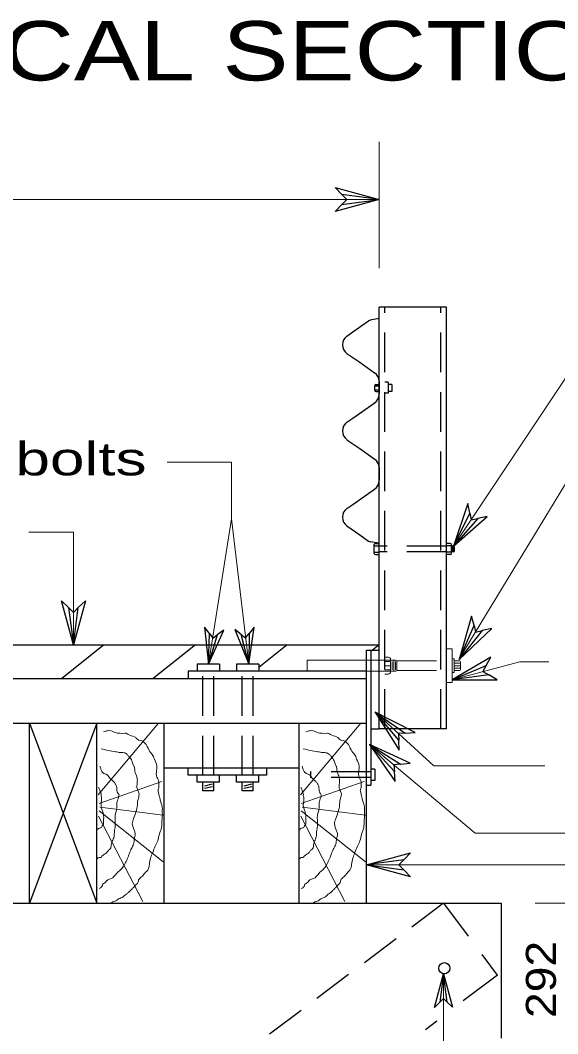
# Model space of a CAD drawing. Extents: x 13426 to 15509, y -9298 to -5111.
# Drawn here: x 15398.12 to 15419.29, y -5515.72 to -5475.82 of the extents above; entities that cross this region are included whole.
import ezdxf
from ezdxf.enums import TextEntityAlignment as Align

# ---------------------------------------------------------------- set-up
doc = ezdxf.new("R2010")
doc.units = 0
doc.header["$LTSCALE"] = 0.52
doc.linetypes.add('MEDIUM_DASHED', pattern=[4.5, 3, -1.5])
for name, color, linetype, lineweight in [('1', 7, 'Continuous', 13), ('15', 7, 'Continuous', 13), ('16', 7, 'Continuous', 25), ('2', 7, 'Continuous', 25), ('20', 7, 'Continuous', 13), ('3', 7, 'Continuous', 25), ('4', 7, 'Continuous', 13), ('5', 7, 'Continuous', 25)]:
    doc.layers.add(name, color=color, linetype=linetype, lineweight=lineweight)
doc.layers.add('19', color=7, linetype='Continuous')

msp = doc.modelspace()

# ---------------------------------------------------------------- linework, layer by layer
at = {"layer": '1'}
for p, q in [((15412.258, -5480.613), (15412.258, -5485.587)), ((15412.258, -5482.878), (15347.53, -5482.878))]:
    msp.add_line(p, q, dxfattribs=at)
at = {"layer": '1', "lineweight": 25}
for p, q in [((15411.219, -5488.094), (15411.843, -5487.655)), ((15412.258, -5487.565), (15411.911, -5487.626)), ((15410.99, -5488.252), (15411.218, -5488.092)), ((15410.99, -5488.939), (15411.493, -5489.286)), ((15411.493, -5489.287), (15412.08, -5489.7)), ((15412.258, -5490.546), (15412.258, -5490.043)), ((15412.258, -5490.043), (15412.258, -5490.546)), ((15411.216, -5491.487), (15412.104, -5490.873)), ((15410.99, -5491.65), (15411.218, -5491.491)), ((15410.99, -5492.333), (15411.492, -5492.684)), ((15411.493, -5492.682), (15412.104, -5493.11)), ((15412.258, -5493.434), (15412.258, -5493.933)), ((15412.258, -5493.933), (15412.258, -5493.434)), ((15410.99, -5495.726), (15411.492, -5496.078)), ((15411.493, -5496.077), (15411.843, -5496.326)), ((15412.257, -5496.413), (15411.91, -5496.354))]:
    msp.add_line(p, q, dxfattribs=at)
for points in [[(15410.99, -5495.043), (15411.218, -5494.884), (15412.08, -5494.281)], [(15342.717, -5510.579), (15417.071, -5510.579), (15417.071, -5515.89)]]:
    msp.add_lwpolyline(points, dxfattribs=at)
for centre, radius, start, end in [((15411.9413, -5487.7915), 0.1669, 100.00085, 124.99926), ((15411.2299, -5488.5954), 0.4173, 124.98392, 235.01553), ((15411.8419, -5490.0422), 0.4173, 359.99953, 55.01553), ((15411.8419, -5490.543), 0.4173, 304.98447, 0.00048), ((15411.2299, -5491.9897), 0.4173, 124.98392, 235.01552), ((15411.2299, -5491.9898), 0.4173, 124.98445, 235.01605), ((15411.8419, -5493.4365), 0.4173, 359.99946, 55.01547), ((15411.8419, -5493.9373), 0.4173, 304.98441, 0.00041), ((15411.2299, -5495.3841), 0.4173, 124.98445, 235.01605), ((15411.939, -5496.1891), 0.1669, 235.00071, 259.99912)]:
    msp.add_arc(centre, radius, start, end, dxfattribs=at)
at = {"layer": '15'}
for p, q in [((15421.463, -5487.1), (15415.189, -5496.522)), ((15406.44, -5493.222), (15403.914, -5493.222)), ((15406.44, -5495.443), (15406.44, -5493.222)), ((15415.416, -5500.962), (15419.597, -5494.065)), ((15405.541, -5501.172), (15406.44, -5495.443)), ((15407.124, -5501.174), (15406.441, -5495.443)), ((15412.103, -5503.054), (15414.407, -5505.17)), ((15411.881, -5504.332), (15416.047, -5507.828)), ((15414.407, -5505.17), (15418.785, -5505.17)), ((15416.047, -5507.828), (15426.412, -5507.828)), ((15411.76, -5509.07), (15425.591, -5509.07)), ((15418.411, -5510.579), (15424.564, -5510.579)), ((15414.792, -5513.359), (15414.796, -5516.375))]:
    msp.add_line(p, q, dxfattribs=at)
at = {"layer": '15', "lineweight": 25}
for p, q in [((15412.134, -5490.156), (15412.258, -5490.156)), ((15412.089, -5490.218), (15412.258, -5490.218)), ((15412.089, -5490.368), (15412.258, -5490.368)), ((15412.134, -5490.433), (15412.258, -5490.433))]:
    msp.add_line(p, q, dxfattribs=at)
at = {"layer": '15', "linetype": 'MEDIUM_DASHED', "lineweight": 25}
for p, q in [((15412.753, -5490.156), (15412.612, -5490.156)), ((15412.753, -5490.433), (15412.612, -5490.433))]:
    msp.add_line(p, q, dxfattribs=at)
at = {"layer": '15'}
for points in [[(15398.461, -5495.973), (15400.214, -5495.973), (15400.214, -5500.409)], [(15415.135, -5501.785), (15417.796, -5501.074), (15418.945, -5501.074)]]:
    msp.add_lwpolyline(points, dxfattribs=at)
at = {"layer": '16'}
for points in [[(15410.794, -5482.687), (15410.523, -5482.405), (15412.258, -5482.878), (15410.523, -5483.351), (15410.794, -5483.069), (15412.258, -5482.878), (15410.794, -5482.687), (15410.985, -5482.878), (15410.794, -5483.069)], [(15415.829, -5495.221), (15415.746, -5494.847), (15415.189, -5496.522), (15416.52, -5495.362), (15416.143, -5495.429), (15415.189, -5496.522), (15415.829, -5495.221), (15415.882, -5495.482), (15416.143, -5495.429)], [(15400.405, -5498.945), (15400.687, -5498.674), (15400.214, -5500.409), (15399.74, -5498.674), (15400.022, -5498.945), (15400.214, -5500.409), (15400.405, -5498.945), (15400.214, -5499.136), (15400.022, -5498.945)], [(15415.996, -5499.653), (15415.897, -5499.283), (15415.411, -5500.981), (15416.692, -5499.764), (15416.318, -5499.848), (15415.411, -5500.981), (15415.996, -5499.653), (15416.059, -5499.912), (15416.318, -5499.848)], [(15405.571, -5499.963), (15405.378, -5499.709), (15405.541, -5501.172), (15406.143, -5499.829), (15405.881, -5500.012), (15405.541, -5501.172), (15405.571, -5499.963), (15405.702, -5500.143), (15405.881, -5500.012)], [(15406.823, -5500), (15406.568, -5499.807), (15407.12, -5501.172), (15407.337, -5499.716), (15407.134, -5499.963), (15407.12, -5501.172), (15406.823, -5500), (15406.997, -5500.137), (15407.134, -5499.963)], [(15416.474, -5501.225), (15416.657, -5500.888), (15415.135, -5501.785), (15416.902, -5501.785), (15416.573, -5501.588), (15415.135, -5501.785), (15416.474, -5501.225), (15416.341, -5501.456), (15416.573, -5501.588)], [(15413.29, -5503.889), (15413.673, -5503.865), (15412.103, -5503.054), (15413.044, -5504.549), (15413.036, -5504.166), (15412.103, -5503.054), (15413.29, -5503.889), (15413.024, -5503.9), (15413.036, -5504.166)], [(15413.103, -5505.112), (15413.485, -5505.071), (15411.881, -5504.332), (15412.887, -5505.783), (15412.861, -5505.401), (15411.881, -5504.332), (15413.103, -5505.112), (15412.839, -5505.135), (15412.861, -5505.401)], [(15413.225, -5509.261), (15413.495, -5509.543), (15411.76, -5509.07), (15413.495, -5508.596), (15413.225, -5508.878), (15411.76, -5509.07), (15413.225, -5509.261), (15413.033, -5509.07), (15413.225, -5508.878)], [(15414.648, -5514.472), (15414.434, -5514.678), (15414.792, -5513.359), (15415.153, -5514.677), (15414.939, -5514.472), (15414.792, -5513.359), (15414.648, -5514.472), (15414.793, -5514.326), (15414.939, -5514.472)]]:
    msp.add_lwpolyline(points, dxfattribs=at)
at = {"layer": '2'}
for p, q in [((15405.974, -5501.174), (15405.088, -5501.174)), ((15405.088, -5501.174), (15405.088, -5501.451)), ((15405.974, -5501.174), (15405.974, -5501.451)), ((15407.523, -5501.174), (15406.638, -5501.174)), ((15406.638, -5501.174), (15406.638, -5501.451)), ((15407.523, -5501.174), (15407.523, -5501.451)), ((15412.093, -5505.301), (15411.926, -5505.301)), ((15412.093, -5505.301), (15412.093, -5505.744)), ((15405.088, -5505.821), (15405.088, -5505.545)), ((15405.974, -5505.821), (15405.974, -5505.545)), ((15406.638, -5505.821), (15406.638, -5505.545)), ((15407.523, -5505.821), (15407.523, -5505.545)), ((15405.974, -5505.821), (15405.088, -5505.821)), ((15405.31, -5506.153), (15405.31, -5505.821)), ((15405.687, -5505.89), (15405.38, -5505.966)), ((15405.689, -5505.992), (15405.381, -5506.069)), ((15405.752, -5506.153), (15405.752, -5505.821)), ((15407.523, -5505.821), (15406.638, -5505.821)), ((15406.859, -5506.153), (15406.859, -5505.821)), ((15407.236, -5505.89), (15406.929, -5505.966)), ((15407.238, -5505.992), (15406.93, -5506.069)), ((15407.301, -5506.153), (15407.301, -5505.821)), ((15412.093, -5505.744), (15411.926, -5505.744)), ((15405.752, -5506.153), (15405.31, -5506.153)), ((15407.301, -5506.153), (15406.859, -5506.153)), ((15414.798, -5510.579), (15415.771, -5511.873)), ((15416.926, -5513.41), (15416.312, -5512.592)), ((15416.926, -5513.41), (15415.57, -5514.428)), ((15414.085, -5515.544), (15414.536, -5515.206))]:
    msp.add_line(p, q, dxfattribs=at)
at = {"layer": '2', "linetype": 'MEDIUM_DASHED'}
for p, q in [((15405.31, -5505.545), (15405.31, -5501.451)), ((15405.752, -5505.545), (15405.752, -5501.451)), ((15406.859, -5505.545), (15406.859, -5501.451)), ((15407.301, -5505.545), (15407.301, -5501.451)), ((15411.926, -5505.633), (15409.548, -5505.633)), ((15414.798, -5510.579), (15406.892, -5516.522))]:
    msp.add_line(p, q, dxfattribs=at)
msp.add_lwpolyline([(15411.926, -5505.412), (15409.548, -5505.412), (15409.548, -5505.633)], dxfattribs=at)
at = {"layer": '2'}
msp.add_circle((15414.8272, -5513.1405), 0.2213, dxfattribs=at)
at = {"layer": '3', "linetype": 'MEDIUM_DASHED'}
for p, q in [((15412.612, -5490.07), (15412.479, -5490.07)), ((15412.612, -5490.07), (15412.612, -5490.507)), ((15412.753, -5490.156), (15412.753, -5490.433)), ((15412.612, -5490.507), (15412.479, -5490.507)), ((15414.913, -5496.522), (15412.258, -5496.522)), ((15414.913, -5496.744), (15412.258, -5496.744))]:
    msp.add_line(p, q, dxfattribs=at)
at = {"layer": '3'}
for p, q in [((15412.089, -5490.388), (15412.089, -5490.2)), ((15412.067, -5496.807), (15412.067, -5496.458)), ((15412.067, -5496.51), (15412.258, -5496.51)), ((15412.112, -5496.414), (15412.257, -5496.414)), ((15415.104, -5496.51), (15414.913, -5496.51)), ((15415.059, -5496.414), (15414.914, -5496.414)), ((15415.104, -5496.807), (15415.104, -5496.458)), ((15415.189, -5496.522), (15415.105, -5496.522)), ((15415.132, -5496.554), (15415.132, -5496.714)), ((15415.179, -5496.554), (15415.179, -5496.714)), ((15412.067, -5496.759), (15412.258, -5496.759)), ((15412.112, -5496.851), (15412.257, -5496.851)), ((15415.104, -5496.759), (15414.913, -5496.759)), ((15415.059, -5496.851), (15414.914, -5496.851)), ((15415.189, -5496.744), (15415.105, -5496.744)), ((15415.233, -5496.699), (15415.233, -5496.566))]:
    msp.add_line(p, q, dxfattribs=at)
for centre, start, end in [((15412.1337, -5490.2002), 90, 180), ((15412.1337, -5490.3882), 180, 270.00003), ((15412.1116, -5496.4581), 90, 180), ((15415.0592, -5496.4581), 0, 90), ((15415.1886, -5496.5666), 0, 90), ((15412.1116, -5496.8073), 180, 269.99999), ((15415.0592, -5496.8073), 270, 0), ((15415.1886, -5496.6994), 270, 0)]:
    msp.add_arc(centre, 0.0443, start, end, dxfattribs=at)
at = {"layer": '4', "lineweight": 25}
for p, q in [((15347.53, -5500.409), (15412.258, -5500.409)), ((15399.743, -5501.728), (15401.4, -5500.409)), ((15405.019, -5500.409), (15403.363, -5501.728)), ((15408.639, -5500.409), (15407.523, -5501.298)), ((15412.258, -5500.409), (15411.992, -5500.621)), ((15348.028, -5501.728), (15411.76, -5501.728)), ((15411.76, -5501.451), (15404.74, -5501.451)), ((15404.74, -5501.451), (15404.74, -5501.728)), ((15411.76, -5510.579), (15411.76, -5501.728)), ((15348.028, -5503.498), (15411.76, -5503.498)), ((15398.483, -5510.579), (15398.483, -5503.498)), ((15398.483, -5503.498), (15401.138, -5510.579)), ((15401.138, -5503.498), (15398.483, -5510.579)), ((15401.138, -5510.579), (15401.138, -5503.498)), ((15403.794, -5510.579), (15403.794, -5503.498)), ((15409.105, -5510.579), (15409.105, -5503.498)), ((15409.105, -5505.268), (15403.794, -5505.268)), ((15404.74, -5505.545), (15404.74, -5505.268)), ((15407.82, -5505.268), (15407.82, -5505.545)), ((15407.82, -5505.545), (15404.74, -5505.545))]:
    msp.add_line(p, q, dxfattribs=at)
at = {"layer": '4'}
for p, q in [((15412.622, -5500.898), (15412.48, -5500.898)), ((15415.135, -5500.567), (15414.914, -5500.567)), ((15415.135, -5500.567), (15415.135, -5501.895)), ((15409.42, -5501.008), (15409.42, -5501.451)), ((15409.42, -5501.008), (15411.76, -5501.008)), ((15412.479, -5501.229), (15412.711, -5501.229)), ((15412.48, -5501.064), (15412.711, -5501.064)), ((15412.711, -5501.472), (15412.711, -5500.987)), ((15412.917, -5501.008), (15412.711, -5501.008)), ((15412.772, -5501.064), (15412.772, -5501.395)), ((15412.836, -5501.008), (15412.836, -5501.451)), ((15412.9, -5501.064), (15412.9, -5501.395)), ((15412.961, -5501.407), (15412.961, -5501.052)), ((15415.218, -5500.954), (15415.135, -5500.954)), ((15415.218, -5500.954), (15415.218, -5501.495)), ((15415.422, -5501.037), (15415.218, -5501.037)), ((15415.218, -5501.134), (15415.466, -5501.134)), ((15415.218, -5501.231), (15415.466, -5501.231)), ((15415.218, -5501.328), (15415.466, -5501.328)), ((15415.466, -5501.38), (15415.466, -5501.081)), ((15412.479, -5501.395), (15412.711, -5501.395)), ((15412.622, -5501.56), (15412.48, -5501.56)), ((15412.917, -5501.451), (15412.711, -5501.451)), ((15415.218, -5501.495), (15415.135, -5501.495)), ((15415.422, -5501.425), (15415.218, -5501.425)), ((15415.135, -5501.895), (15414.914, -5501.895)), ((15403.569, -5503.497), (15401.191, -5506.317)), ((15411.536, -5503.497), (15409.157, -5506.317)), ((15403.701, -5505.79), (15401.223, -5506.657)), ((15411.667, -5505.79), (15409.19, -5506.657)), ((15403.749, -5507.116), (15401.256, -5506.793)), ((15411.716, -5507.116), (15409.223, -5506.793)), ((15402.946, -5510.514), (15401.207, -5507.15)), ((15403.749, -5508.951), (15401.223, -5506.946)), ((15410.912, -5510.514), (15409.173, -5507.15)), ((15411.716, -5508.951), (15409.19, -5506.946))]:
    msp.add_line(p, q, dxfattribs=at)
at = {"layer": '4', "linetype": 'MEDIUM_DASHED'}
for p, q in [((15412.711, -5501.008), (15411.76, -5501.008)), ((15412.958, -5501.037), (15415.218, -5501.037)), ((15411.76, -5501.451), (15412.711, -5501.451)), ((15412.958, -5501.425), (15415.218, -5501.425))]:
    msp.add_line(p, q, dxfattribs=at)
at = {"layer": '4'}
for centre, radius, start, end in [((15412.6225, -5500.987), 0.0885, 0.00001, 90), ((15412.9166, -5501.0524), 0.0443, 0.00001, 90), ((15415.4215, -5501.0814), 0.0443, 0.00001, 90), ((15412.6225, -5501.4719), 0.0885, 270, 0), ((15412.9166, -5501.4065), 0.0443, 270, 0), ((15415.4215, -5501.3801), 0.0443, 270, 0)]:
    msp.add_arc(centre, radius, start, end, dxfattribs=at)
for points in [[(15401.404, -5503.837), (15401.634, -5503.786), (15401.847, -5503.854), (15402.257, -5503.888), (15402.29, -5503.888), (15402.372, -5503.939), (15402.618, -5504.024), (15402.716, -5504.108), (15402.782, -5504.159), (15402.798, -5504.159), (15403.061, -5504.312), (15403.126, -5504.414), (15403.258, -5504.652), (15403.323, -5504.72), (15403.405, -5504.907), (15403.504, -5505.179), (15403.504, -5505.281), (15403.487, -5505.57), (15403.569, -5505.756), (15403.586, -5505.926), (15403.569, -5506.062), (15403.552, -5506.113), (15403.552, -5506.164), (15403.569, -5506.232), (15403.586, -5506.317), (15403.618, -5506.436), (15403.635, -5506.521), (15403.684, -5506.674), (15403.717, -5506.81), (15403.717, -5506.929), (15403.717, -5507.116), (15403.701, -5507.32), (15403.684, -5507.608), (15403.602, -5507.863), (15403.536, -5508.118), (15403.438, -5508.339), (15403.34, -5508.577), (15403.258, -5508.798), (15403.208, -5509.052), (15403.143, -5509.273), (15403.028, -5509.392), (15402.897, -5509.545), (15402.782, -5509.664), (15402.765, -5509.732), (15402.733, -5509.8), (15402.667, -5509.868), (15402.568, -5509.97), (15402.486, -5510.055), (15402.388, -5510.157), (15402.29, -5510.225), (15402.175, -5510.327), (15401.994, -5510.412), (15401.929, -5510.463), (15401.847, -5510.497), (15401.765, -5510.53), (15401.617, -5510.582), (15401.616, -5510.582)], [(15409.37, -5503.837), (15409.6, -5503.786), (15409.813, -5503.854), (15410.223, -5503.888), (15410.256, -5503.888), (15410.338, -5503.939), (15410.584, -5504.024), (15410.683, -5504.108), (15410.748, -5504.159), (15410.765, -5504.159), (15411.027, -5504.312), (15411.093, -5504.414), (15411.224, -5504.652), (15411.29, -5504.72), (15411.372, -5504.907), (15411.47, -5505.179), (15411.47, -5505.281), (15411.454, -5505.57), (15411.536, -5505.756), (15411.552, -5505.926), (15411.536, -5506.062), (15411.519, -5506.113), (15411.519, -5506.164), (15411.536, -5506.232), (15411.552, -5506.317), (15411.585, -5506.436), (15411.601, -5506.521), (15411.651, -5506.674), (15411.683, -5506.81), (15411.683, -5506.929), (15411.683, -5507.116), (15411.667, -5507.32), (15411.651, -5507.608), (15411.569, -5507.863), (15411.503, -5508.118), (15411.404, -5508.339), (15411.306, -5508.577), (15411.224, -5508.798), (15411.175, -5509.052), (15411.109, -5509.273), (15410.994, -5509.392), (15410.863, -5509.545), (15410.748, -5509.664), (15410.732, -5509.732), (15410.699, -5509.8), (15410.633, -5509.868), (15410.535, -5509.97), (15410.453, -5510.055), (15410.354, -5510.157), (15410.256, -5510.225), (15410.141, -5510.327), (15409.961, -5510.412), (15409.895, -5510.463), (15409.813, -5510.497), (15409.731, -5510.53), (15409.584, -5510.582), (15409.582, -5510.582)], [(15401.306, -5504.499), (15401.584, -5504.567), (15401.879, -5504.618), (15401.978, -5504.635), (15402.109, -5504.652), (15402.158, -5504.652), (15402.306, -5504.703), (15402.322, -5504.72), (15402.404, -5504.805), (15402.519, -5504.975), (15402.568, -5505.128), (15402.618, -5505.23), (15402.634, -5505.383), (15402.7, -5505.57), (15402.733, -5505.739), (15402.716, -5505.96), (15402.733, -5506.096), (15402.798, -5506.232), (15402.798, -5506.351), (15402.749, -5506.538), (15402.733, -5506.708), (15402.585, -5507.251), (15402.536, -5507.455), (15402.618, -5507.727), (15402.65, -5507.863), (15402.618, -5508.033), (15402.585, -5508.254), (15402.503, -5508.424), (15402.421, -5508.611), (15402.339, -5508.832), (15402.29, -5508.933), (15402.191, -5509.121), (15402.06, -5509.273), (15401.929, -5509.392), (15401.699, -5509.613), (15401.634, -5509.63), (15401.568, -5509.664), (15401.518, -5509.698), (15401.47, -5509.766), (15401.355, -5509.851), (15401.355, -5509.885), (15401.306, -5509.953), (15401.289, -5509.97), (15401.223, -5510.004)], [(15409.272, -5504.499), (15409.551, -5504.567), (15409.846, -5504.618), (15409.945, -5504.635), (15410.075, -5504.652), (15410.125, -5504.652), (15410.272, -5504.703), (15410.289, -5504.72), (15410.371, -5504.805), (15410.486, -5504.975), (15410.535, -5505.128), (15410.584, -5505.23), (15410.601, -5505.383), (15410.666, -5505.57), (15410.699, -5505.739), (15410.683, -5505.96), (15410.699, -5506.096), (15410.765, -5506.232), (15410.765, -5506.351), (15410.715, -5506.538), (15410.699, -5506.708), (15410.551, -5507.251), (15410.502, -5507.455), (15410.584, -5507.727), (15410.617, -5507.863), (15410.584, -5508.033), (15410.551, -5508.254), (15410.469, -5508.424), (15410.387, -5508.611), (15410.306, -5508.832), (15410.256, -5508.933), (15410.158, -5509.121), (15410.027, -5509.273), (15409.895, -5509.392), (15409.666, -5509.613), (15409.6, -5509.63), (15409.534, -5509.664), (15409.485, -5509.698), (15409.436, -5509.766), (15409.321, -5509.851), (15409.321, -5509.885), (15409.272, -5509.953), (15409.256, -5509.97), (15409.19, -5510.004)], [(15401.256, -5505.179), (15401.289, -5505.281), (15401.338, -5505.4), (15401.453, -5505.485), (15401.502, -5505.502), (15401.584, -5505.57), (15401.699, -5505.705), (15401.797, -5505.79), (15401.863, -5505.875), (15401.912, -5505.978), (15401.945, -5506.198), (15402.011, -5506.317), (15401.994, -5506.419), (15401.929, -5506.623), (15401.929, -5506.827), (15401.863, -5507.116), (15401.863, -5507.541), (15401.83, -5507.761), (15401.814, -5507.965), (15401.748, -5508.135), (15401.699, -5508.339), (15401.666, -5508.441), (15401.6, -5508.492), (15401.535, -5508.577), (15401.338, -5508.73), (15401.289, -5508.781), (15401.256, -5508.781), (15401.141, -5508.832)], [(15409.223, -5505.179), (15409.256, -5505.281), (15409.305, -5505.4), (15409.42, -5505.485), (15409.469, -5505.502), (15409.551, -5505.57), (15409.666, -5505.705), (15409.764, -5505.79), (15409.83, -5505.875), (15409.879, -5505.978), (15409.911, -5506.198), (15409.977, -5506.317), (15409.961, -5506.419), (15409.895, -5506.623), (15409.895, -5506.827), (15409.83, -5507.116), (15409.83, -5507.541), (15409.797, -5507.761), (15409.781, -5507.965), (15409.715, -5508.135), (15409.666, -5508.339), (15409.633, -5508.441), (15409.567, -5508.492), (15409.502, -5508.577), (15409.305, -5508.73), (15409.256, -5508.781), (15409.223, -5508.781), (15409.108, -5508.832)], [(15401.207, -5506.011), (15401.256, -5506.13), (15401.273, -5506.198), (15401.306, -5506.266), (15401.306, -5506.334), (15401.322, -5506.402), (15401.322, -5506.453), (15401.322, -5506.521), (15401.306, -5506.691), (15401.322, -5506.844), (15401.371, -5506.98), (15401.404, -5507.132), (15401.404, -5507.439), (15401.388, -5507.506), (15401.371, -5507.506), (15401.338, -5507.574), (15401.24, -5507.625), (15401.174, -5507.659), (15401.125, -5507.693)], [(15409.173, -5506.011), (15409.223, -5506.13), (15409.239, -5506.198), (15409.272, -5506.266), (15409.272, -5506.334), (15409.288, -5506.402), (15409.288, -5506.453), (15409.288, -5506.521), (15409.272, -5506.691), (15409.288, -5506.844), (15409.338, -5506.98), (15409.37, -5507.132), (15409.37, -5507.439), (15409.354, -5507.506), (15409.338, -5507.506), (15409.305, -5507.574), (15409.206, -5507.625), (15409.141, -5507.659), (15409.091, -5507.693)]]:
    msp.add_spline(points, degree=3, dxfattribs=at)
at = {"layer": '5', "linetype": 'MEDIUM_DASHED'}
for p, q in [((15412.479, -5503.719), (15412.479, -5487.122)), ((15414.692, -5503.719), (15414.692, -5487.122))]:
    msp.add_line(p, q, dxfattribs=at)
at = {"layer": '5'}
for p, q in [((15411.76, -5501.728), (15411.76, -5500.621)), ((15411.926, -5500.621), (15411.926, -5505.932)), ((15414.914, -5503.719), (15412.258, -5503.719)), ((15411.76, -5505.932), (15411.926, -5505.932))]:
    msp.add_line(p, q, dxfattribs=at)
for points in [[(15411.926, -5503.719), (15412.258, -5503.719), (15412.258, -5487.122)], [(15414.914, -5503.719), (15414.914, -5487.122), (15412.258, -5487.122)], [(15411.76, -5500.621), (15411.926, -5500.621), (15412.258, -5500.621)]]:
    msp.add_lwpolyline(points, dxfattribs=at)

# ---------------------------------------------------------------- texts
at = {"layer": '19', "width": 1.4}
msp.add_text('M24 bolts', height=1.307, dxfattribs=at).set_placement((15403.098, -5493.738), align=Align.RIGHT)
at = {"layer": '19', "width": 1.15}
msp.add_text('292', height=1.184, rotation=90, dxfattribs=at).set_placement((15419.223, -5513.5805), align=Align.CENTER)
at = {"layer": '20', "width": 1.25}
msp.add_text('TYPICAL SECTION-TWO LANE BRIDGE', height=2.333, dxfattribs=at).set_placement((15424.934, -5478.191), align=Align.CENTER)

doc.saveas('drawing.dxf')
